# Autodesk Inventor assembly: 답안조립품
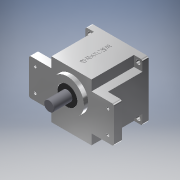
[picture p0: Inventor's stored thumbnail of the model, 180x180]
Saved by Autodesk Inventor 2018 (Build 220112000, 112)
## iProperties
Created: 2020-07
Part Number: 답안조립품
Material: 일반
Document SubType Name: Assembly
Designer: Admin
Author: Admin
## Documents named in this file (10)
- C:\Users\Admin\Desktop\700707V1010\답안조립품.iam
- C:\Users\Admin\Desktop\700707V1010\본체.ipt
- C:\Users\Admin\Desktop\700707V1010\커버.ipt
- C:\Users\Admin\Desktop\700707V1010\메인 축.ipt
- C:\Users\Admin\Desktop\700707V1010\서브 축.ipt
- C:\Users\Admin\Desktop\700707V1010\볼트 M4.ipt
- C:\Users\Admin\Desktop\700707V1010\베어링 6003.ipt
- C:\Users\Admin\Desktop\700707V1010\베어링 608.ipt
- C:\Users\Admin\Desktop\700707V1010\오일 실 17 32 8.ipt
- C:\Users\Admin\Desktop\700707V1010\오일 실 8 22 7.ipt
